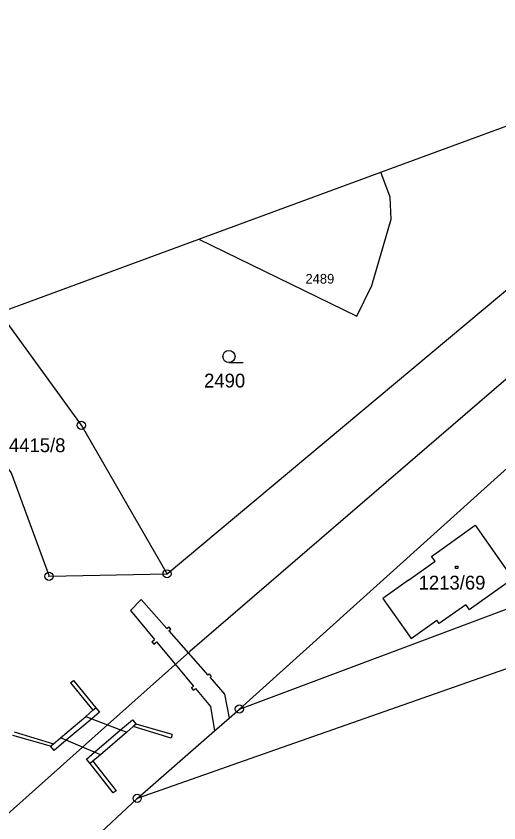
# Model space of a CAD drawing. Extents: x -468021 to -466942, y -1130484 to -1128584.
# Drawn here: x -467694.3 to -467634.9, y -1130033.4 to -1129934.4 of the extents above; entities that cross this region are included whole.
import ezdxf

# ---------------------------------------------------------------- set-up
doc = ezdxf.new("R2010")
doc.units = 0
doc.layers.add('DKM', color=7, linetype='Continuous')

msp = doc.modelspace()

# ---------------------------------------------------------------- linework, layer by layer
at = {"layer": 'DKM'}
for p, q in [((-467649.4, -1129953.51), (-467597.27, -1129934.35)), ((-467671.78, -1129961.73), (-467649.4, -1129953.51)), ((-467648.26, -1129956.57), (-467649.4, -1129953.51)), ((-467648.15, -1129959.3), (-467648.26, -1129956.57)), ((-467675.69, -1130002.85), (-467623.23, -1129959.01)), ((-467650.51, -1129967.45), (-467648.15, -1129959.3)), ((-467696.3, -1129970.74), (-467671.78, -1129961.73)), ((-467671.78, -1129961.73), (-467660.5, -1129967.24)), ((-467615.83, -1129963.32), (-467672.89, -1130012.41)), ((-467660.5, -1129967.24), (-467652.35, -1129971.22)), ((-467652.35, -1129971.22), (-467650.51, -1129967.45)), ((-467686.23, -1129984.61), (-467696.3, -1129970.74)), ((-467666.8, -1130019.47), (-467534.68, -1129970.03)), ((-467668.08, -1129976.91), (-467666.33, -1129976.91)), ((-467675.69, -1130002.85), (-467686.23, -1129984.61)), ((-467633.4, -1129989.46), (-467666.8, -1130019.47)), ((-467643.16, -1130000.72), (-467637.81, -1129996.89)), ((-467637.81, -1129996.89), (-467633.16, -1130003.48)), ((-467645.99, -1130003.62), (-467642.73, -1130001.32)), ((-467642.73, -1130001.32), (-467643.16, -1130000.72)), ((-467640.23, -1130001.9), (-467639.93, -1130001.9)), ((-467640.23, -1130002.2), (-467640.23, -1130001.9)), ((-467639.93, -1130002.2), (-467640.23, -1130002.2)), ((-467639.93, -1130001.9), (-467639.93, -1130002.2)), ((-467633.16, -1130003.48), (-467638.52, -1130007.28)), ((-467604.59, -1130004.24), (-467667.01, -1130026.11)), ((-467680.2, -1130007.35), (-467678.86, -1130006.01)), ((-467678.86, -1130006.01), (-467675.72, -1130009.57)), ((-467680.2, -1130007.35), (-467677.24, -1130010.91)), ((-467638.95, -1130006.67), (-467642.21, -1130008.97)), ((-467638.95, -1130006.67), (-467638.52, -1130007.28)), ((-467642.21, -1130008.97), (-467642.52, -1130008.54)), ((-467675.72, -1130009.57), (-467675.48, -1130009.35)), ((-467675.22, -1130009.65), (-467675.48, -1130009.35)), ((-467675.46, -1130009.86), (-467675.22, -1130009.65)), ((-467675.46, -1130009.86), (-467670.68, -1130015.29)), ((-467677.58, -1130011.21), (-467677.24, -1130010.91)), ((-467677.58, -1130011.21), (-467677.32, -1130011.51)), ((-467677.32, -1130011.51), (-467676.99, -1130011.21)), ((-467676.99, -1130011.21), (-467672.46, -1130016.66)), ((-467672.89, -1130012.41), (-467683.02, -1130021.4)), ((-467670.68, -1130015.29), (-467670.5, -1130015.15)), ((-467670.5, -1130015.15), (-467670.26, -1130015.47)), ((-467670.41, -1130015.59), (-467670.26, -1130015.47)), ((-467687.55, -1130016.23), (-467687.2, -1130015.95)), ((-467687.55, -1130016.23), (-467684.8, -1130019.61)), ((-467687.2, -1130015.95), (-467684.46, -1130019.32)), ((-467670.41, -1130015.59), (-467668.61, -1130017.63)), ((-467672.7, -1130016.84), (-467672.46, -1130016.66)), ((-467672.46, -1130017.16), (-467672.7, -1130016.84)), ((-467672.46, -1130017.16), (-467672.2, -1130016.96)), ((-467672.2, -1130016.96), (-467670.37, -1130019.17)), ((-467668.61, -1130017.63), (-467668.06, -1130020.57)), ((-467684.8, -1130019.61), (-467684.46, -1130019.32)), ((-467684.46, -1130019.32), (-467684.01, -1130019.85)), ((-467670.37, -1130019.17), (-467669.84, -1130022.13)), ((-467688.8, -1130023.01), (-467685.7, -1130020.38)), ((-467685.7, -1130020.38), (-467684.8, -1130019.61)), ((-467685.7, -1130020.38), (-467684.96, -1130020.66)), ((-467684.01, -1130019.85), (-467684.96, -1130020.66)), ((-467668.06, -1130020.57), (-467666.8, -1130019.47)), ((-467684.96, -1130020.66), (-467688.08, -1130023.31)), ((-467683.02, -1130021.4), (-467686.1, -1130024.14)), ((-467684.96, -1130020.66), (-467683.02, -1130021.4)), ((-467683.02, -1130021.4), (-467681.4, -1130022.02)), ((-467681.4, -1130022.02), (-467679.96, -1130020.79)), ((-467679.96, -1130020.79), (-467679.5, -1130021.32)), ((-467679.5, -1130021.32), (-467679.84, -1130021.61)), ((-467675.05, -1130022.61), (-467679.5, -1130021.32)), ((-467669.84, -1130022.13), (-467668.06, -1130020.57)), ((-467694.51, -1130022.27), (-467689.67, -1130023.75)), ((-467684.6, -1130024.78), (-467681.4, -1130022.02)), ((-467680.65, -1130022.31), (-467683.88, -1130025.08)), ((-467681.4, -1130022.02), (-467680.65, -1130022.31)), ((-467679.84, -1130021.61), (-467680.65, -1130022.31)), ((-467675.18, -1130023.04), (-467679.84, -1130021.61)), ((-467679.37, -1130030.44), (-467669.84, -1130022.13)), ((-467690.01, -1130024.04), (-467694.64, -1130022.7)), ((-467689.67, -1130023.75), (-467688.8, -1130023.01)), ((-467688.08, -1130023.31), (-467689.56, -1130024.57)), ((-467688.08, -1130023.31), (-467688.8, -1130023.01)), ((-467686.1, -1130024.14), (-467688.08, -1130023.31)), ((-467675.05, -1130022.61), (-467675.18, -1130023.04)), ((-467686.1, -1130024.14), (-467699.43, -1130035.98)), ((-467690.01, -1130024.04), (-467689.67, -1130023.75)), ((-467689.56, -1130024.57), (-467690.01, -1130024.04)), ((-467684.6, -1130024.78), (-467686.1, -1130024.14)), ((-467685.61, -1130025.64), (-467684.6, -1130024.78)), ((-467683.88, -1130025.08), (-467684.81, -1130025.88)), ((-467683.88, -1130025.08), (-467684.6, -1130024.78)), ((-467685.15, -1130026.17), (-467685.61, -1130025.64)), ((-467684.81, -1130025.88), (-467685.15, -1130026.17)), ((-467682.3, -1130029.78), (-467685.15, -1130026.17)), ((-467684.81, -1130025.88), (-467681.95, -1130029.5)), ((-467667.01, -1130026.11), (-467669.01, -1130026.81)), ((-467669.01, -1130026.81), (-467679.37, -1130030.44)), ((-467681.95, -1130029.5), (-467682.3, -1130029.78)), ((-467679.37, -1130030.44), (-467724.09, -1130072.13))]:
    msp.add_line(p, q, dxfattribs=at)
for points in [[(-467707.06, -1129974.55), (-467694.87, -1129990.45), (-467690.21, -1130003.16), (-467675.69, -1130002.85)], [(-467645.99, -1130003.62), (-467649.16, -1130005.89), (-467645.67, -1130010.82), (-467642.52, -1130008.54)]]:
    msp.add_lwpolyline(points, dxfattribs=at)
for centre, radius in [((-467668.08, -1129976.16), 0.75), ((-467686.23, -1129984.61), 0.5), ((-467686.23, -1129984.61), 0.01), ((-467675.69, -1130002.85), 0.5), ((-467690.21, -1130003.16), 0.5), ((-467690.21, -1130003.16), 0.01), ((-467675.69, -1130002.85), 0.01), ((-467666.8, -1130019.47), 0.5), ((-467666.8, -1130019.47), 0.01), ((-467679.37, -1130030.44), 0.5), ((-467679.37, -1130030.44), 0.01)]:
    msp.add_circle(centre, radius, dxfattribs=at)

# ---------------------------------------------------------------- texts
for s, height, p in [('2489', 1.19, (-467658.67, -1129967.21)), ('2490', 1.7, (-467671.14, -1129979.97)), ('4415/8', 1.7, (-467695.141, -1129987.91)), ('1213/69', 1.7, (-467644.756, -1130004.79))]:
    msp.add_text(s, height=height, dxfattribs=at).set_placement(p)

doc.saveas('drawing.dxf')
